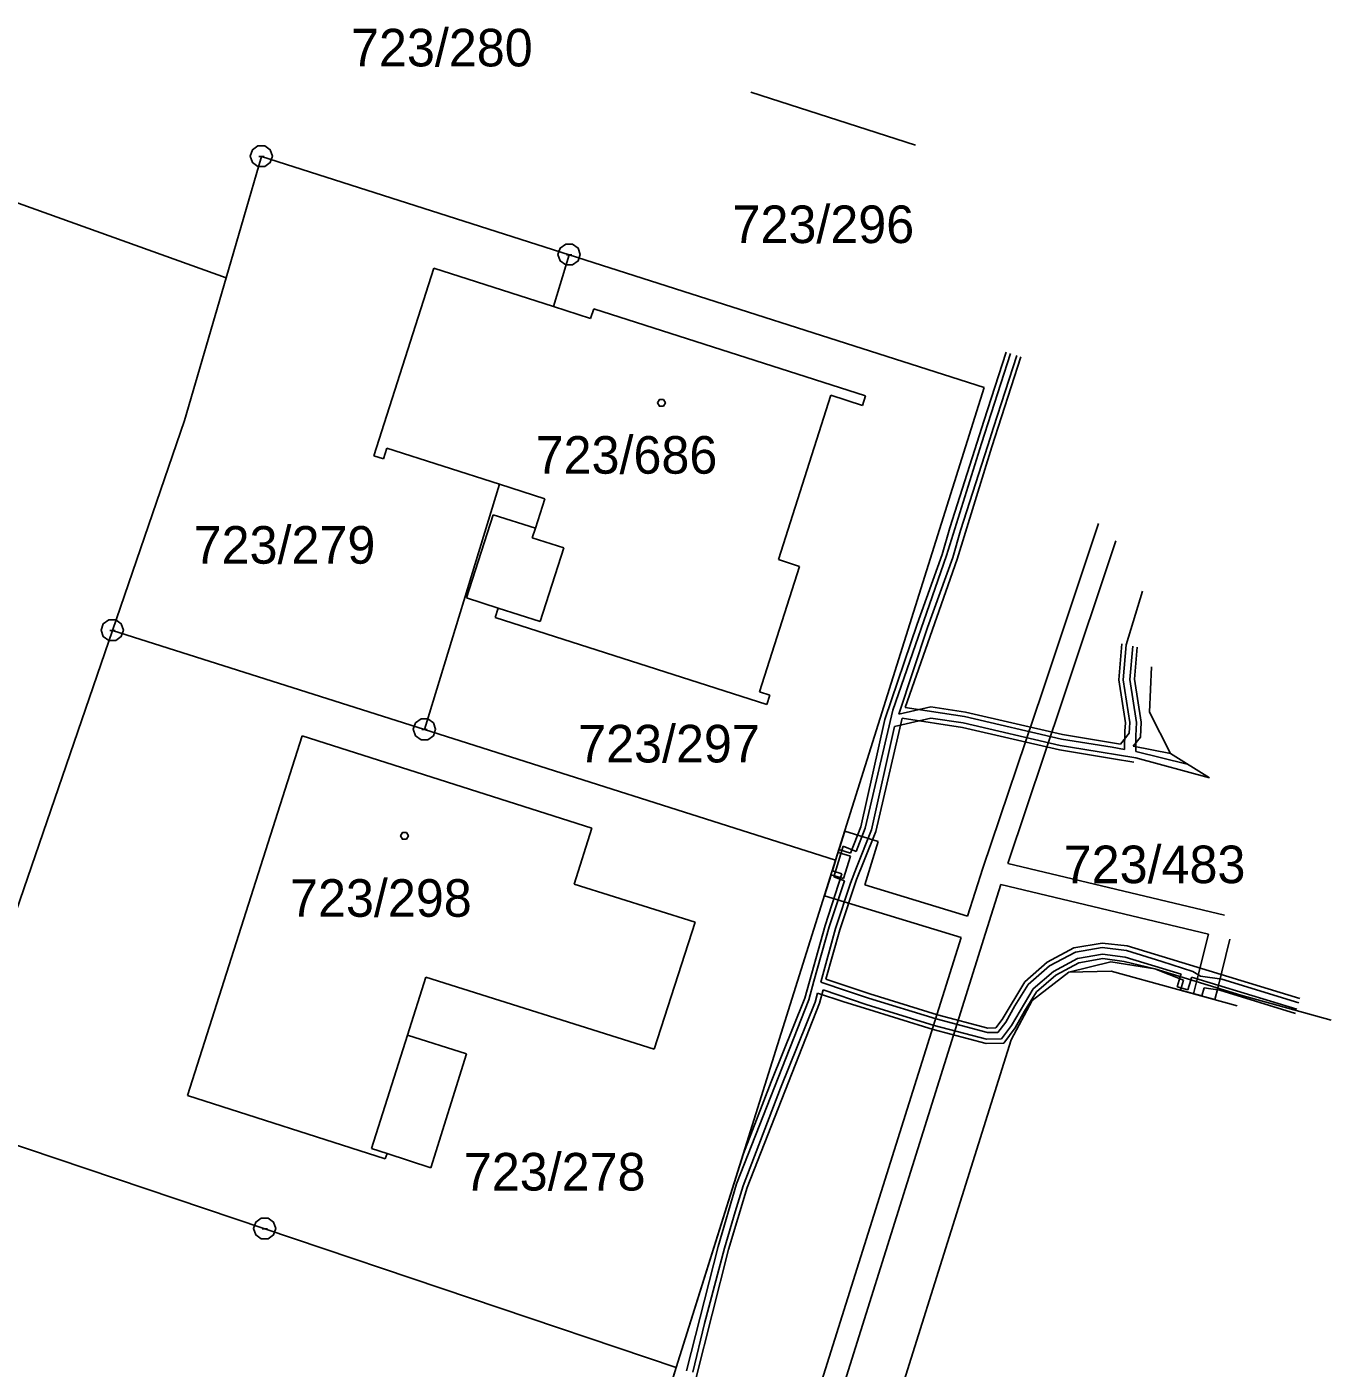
# Model space of a CAD drawing. Extents: x -759060 to -757386, y -1172273 to -1170948.
# Drawn here: x -757479 to -757420, y -1171073 to -1171012.4 of the extents above; entities that cross this region are included whole.
import ezdxf

# ---------------------------------------------------------------- set-up
doc = ezdxf.new("R2010")
doc.units = 0
for name, color, linetype in [('Vrstva 1', 7, 'Continuous'), ('Vrstva 12', 7, 'Continuous'), ('Vrstva 13', 7, 'Continuous'), ('Vrstva 2', 7, 'Continuous'), ('Vrstva 4', 7, 'Continuous'), ('Vrstva 5', 7, 'Continuous'), ('Vrstva 7', 7, 'Continuous'), ('Vrstva 8', 7, 'Continuous')]:
    doc.layers.add(name, color=color, linetype=linetype)

msp = doc.modelspace()

# ---------------------------------------------------------------- linework, layer by layer
at = {"layer": 'Vrstva 1'}
for p, q in [((-757438.84, -1171017.71), (-757446.28, -1171015.32)), ((-757446.28, -1171015.32), (-757446.28, -1171015.32)), ((-757470.02, -1171023.71), (-757490.64, -1171016.31)), ((-757438.84, -1171017.71), (-757438.84, -1171017.71)), ((-757468.42, -1171018.22), (-757470.02, -1171023.71)), ((-757454.5, -1171022.67), (-757468.42, -1171018.22)), ((-757468.42, -1171018.22), (-757468.42, -1171018.22)), ((-757455.21, -1171025.01), (-757454.5, -1171022.67)), ((-757435.73, -1171028.67), (-757454.5, -1171022.67)), ((-757454.5, -1171022.67), (-757454.5, -1171022.67)), ((-757463.33, -1171031.76), (-757460.62, -1171023.28)), ((-757460.62, -1171023.28), (-757455.21, -1171025.01)), ((-757470.02, -1171023.71), (-757471.9, -1171030.17)), ((-757455.21, -1171025.01), (-757453.53, -1171025.55)), ((-757453.53, -1171025.55), (-757453.39, -1171025.12)), ((-757453.39, -1171025.12), (-757441.1, -1171029.05)), ((-757435.73, -1171028.67), (-757442.45, -1171050.05)), ((-757435.73, -1171028.67), (-757435.73, -1171028.67)), ((-757442.67, -1171029.02), (-757445.04, -1171036.45)), ((-757441.24, -1171029.48), (-757442.67, -1171029.02)), ((-757441.1, -1171029.05), (-757441.24, -1171029.48)), ((-757471.9, -1171030.17), (-757475.16, -1171039.66)), ((-757462.9, -1171031.9), (-757463.33, -1171031.76)), ((-757462.75, -1171031.42), (-757462.9, -1171031.9)), ((-757457.66, -1171033.05), (-757462.75, -1171031.42)), ((-757461.04, -1171044.14), (-757457.66, -1171033.05)), ((-757455.61, -1171033.71), (-757457.66, -1171033.05)), ((-757456.03, -1171035.04), (-757455.61, -1171033.71)), ((-757459.14, -1171038.19), (-757457.94, -1171034.43)), ((-757457.94, -1171034.43), (-757456.03, -1171035.04)), ((-757444.09, -1171036.76), (-757445.9, -1171042.43)), ((-757445.04, -1171036.45), (-757444.09, -1171036.76)), ((-757457.71, -1171038.65), (-757459.14, -1171038.19)), ((-757457.85, -1171039.08), (-757457.71, -1171038.65)), ((-757445.56, -1171043.01), (-757457.85, -1171039.08)), ((-757475.16, -1171039.66), (-757482.77, -1171061.83)), ((-757461.04, -1171044.14), (-757475.16, -1171039.66)), ((-757428.17, -1171041.31), (-757428.26, -1171043.35)), ((-757428.17, -1171041.31), (-757428.17, -1171041.31)), ((-757445.9, -1171042.43), (-757445.43, -1171042.58)), ((-757445.43, -1171042.58), (-757445.56, -1171043.01)), ((-757428.26, -1171043.35), (-757428.26, -1171043.35)), ((-757428.26, -1171043.35), (-757427.3, -1171045.23)), ((-757471.77, -1171060.69), (-757466.58, -1171044.43)), ((-757466.58, -1171044.43), (-757453.48, -1171048.6)), ((-757442.45, -1171050.05), (-757461.04, -1171044.14)), ((-757427.3, -1171045.23), (-757425.55, -1171046.32)), ((-757425.55, -1171046.32), (-757425.55, -1171046.32)), ((-757453.48, -1171048.6), (-757454.28, -1171051.13)), ((-757442.45, -1171050.05), (-757449.66, -1171073)), ((-757454.28, -1171051.13), (-757448.8, -1171052.86)), ((-757448.8, -1171052.86), (-757450.66, -1171058.6)), ((-757431.91, -1171055.11), (-757430, -1171054.64)), ((-757430, -1171054.64), (-757428.02, -1171054.97)), ((-757428.02, -1171054.97), (-757424.13, -1171056.16)), ((-757460.99, -1171055.34), (-757461.82, -1171057.96)), ((-757450.66, -1171058.6), (-757460.99, -1171055.34)), ((-757433.57, -1171056.39), (-757431.91, -1171055.11)), ((-757431.91, -1171055.11), (-757429.99, -1171055.07)), ((-757429.99, -1171055.07), (-757424.29, -1171056.63)), ((-757424.13, -1171056.16), (-757420.04, -1171057.29)), ((-757434.52, -1171058.18), (-757433.57, -1171056.39)), ((-757424.29, -1171056.63), (-757424.29, -1171056.63)), ((-757420.04, -1171057.29), (-757420.04, -1171057.29)), ((-757461.82, -1171057.96), (-757459.14, -1171058.81)), ((-757445.57, -1171093.36), (-757434.52, -1171058.18)), ((-757459.14, -1171058.81), (-757460.76, -1171063.97)), ((-757462.82, -1171063.55), (-757471.77, -1171060.69)), ((-757482.77, -1171061.83), (-757468.27, -1171066.72)), ((-757462.73, -1171063.32), (-757462.82, -1171063.55)), ((-757460.76, -1171063.97), (-757462.73, -1171063.32)), ((-757449.66, -1171073), (-757468.27, -1171066.72)), ((-757449.66, -1171073), (-757453.18, -1171084.22))]:
    msp.add_line(p, q, dxfattribs=at)
at = {"layer": 'Vrstva 12'}
for p, q in [((-757438.84, -1171017.71), (-757446.28, -1171015.32)), ((-757446.28, -1171015.32), (-757446.28, -1171015.32)), ((-757438.84, -1171017.71), (-757438.84, -1171017.71)), ((-757463.33, -1171031.76), (-757460.62, -1171023.28)), ((-757460.62, -1171023.28), (-757455.21, -1171025.01)), ((-757455.21, -1171025.01), (-757453.53, -1171025.55)), ((-757453.53, -1171025.55), (-757453.39, -1171025.12)), ((-757453.39, -1171025.12), (-757441.1, -1171029.05)), ((-757442.67, -1171029.02), (-757445.04, -1171036.45)), ((-757441.24, -1171029.48), (-757442.67, -1171029.02)), ((-757441.1, -1171029.05), (-757441.24, -1171029.48)), ((-757462.9, -1171031.9), (-757463.33, -1171031.76)), ((-757462.75, -1171031.42), (-757462.9, -1171031.9)), ((-757457.66, -1171033.05), (-757462.75, -1171031.42)), ((-757455.61, -1171033.71), (-757457.66, -1171033.05)), ((-757456.03, -1171035.04), (-757455.61, -1171033.71)), ((-757456.17, -1171035.47), (-757456.03, -1171035.04)), ((-757454.74, -1171035.93), (-757456.17, -1171035.47)), ((-757455.81, -1171039.26), (-757454.74, -1171035.93)), ((-757444.09, -1171036.76), (-757445.9, -1171042.43)), ((-757445.04, -1171036.45), (-757444.09, -1171036.76)), ((-757457.85, -1171039.08), (-757457.71, -1171038.65)), ((-757445.56, -1171043.01), (-757457.85, -1171039.08)), ((-757457.71, -1171038.65), (-757455.81, -1171039.26)), ((-757445.9, -1171042.43), (-757445.43, -1171042.58)), ((-757445.43, -1171042.58), (-757445.56, -1171043.01)), ((-757471.77, -1171060.69), (-757466.58, -1171044.43)), ((-757466.58, -1171044.43), (-757453.48, -1171048.6)), ((-757453.48, -1171048.6), (-757454.28, -1171051.13)), ((-757454.28, -1171051.13), (-757448.8, -1171052.86)), ((-757448.8, -1171052.86), (-757450.66, -1171058.6)), ((-757460.99, -1171055.34), (-757461.82, -1171057.96)), ((-757450.66, -1171058.6), (-757460.99, -1171055.34)), ((-757461.82, -1171057.96), (-757463.44, -1171063.09)), ((-757462.82, -1171063.55), (-757471.77, -1171060.69)), ((-757463.44, -1171063.09), (-757462.73, -1171063.32)), ((-757462.73, -1171063.32), (-757462.82, -1171063.55))]:
    msp.add_line(p, q, dxfattribs=at)
at = {"layer": 'Vrstva 13'}
for p, q in [((-757435.75, -1171030.2), (-757434.74, -1171027.08)), ((-757434.74, -1171027.08), (-757434.74, -1171027.08)), ((-757435.86, -1171031.21), (-757434.55, -1171027.14)), ((-757434.07, -1171027.29), (-757435.38, -1171031.36)), ((-757434.26, -1171027.22), (-757435.31, -1171030.48)), ((-757434.55, -1171027.14), (-757434.55, -1171027.14)), ((-757434.26, -1171027.22), (-757434.26, -1171027.22)), ((-757434.07, -1171027.29), (-757434.07, -1171027.29)), ((-757436.05, -1171031.14), (-757435.75, -1171030.2)), ((-757435.31, -1171030.48), (-757435.57, -1171031.3)), ((-757437.44, -1171036.27), (-757435.86, -1171031.21)), ((-757437.29, -1171035.02), (-757436.05, -1171031.14)), ((-757435.38, -1171031.36), (-757436.96, -1171036.43)), ((-757435.57, -1171031.3), (-757436.81, -1171035.14)), ((-757433.1, -1171042.42), (-757430.57, -1171034.83)), ((-757430.57, -1171034.83), (-757430.57, -1171034.83)), ((-757437.63, -1171036.22), (-757437.29, -1171035.02)), ((-757436.81, -1171035.14), (-757437.15, -1171036.36)), ((-757429.78, -1171035.6), (-757432.16, -1171042.74)), ((-757429.78, -1171035.6), (-757429.78, -1171035.6)), ((-757438.77, -1171039.38), (-757437.63, -1171036.22)), ((-757439.87, -1171043.27), (-757437.44, -1171036.27)), ((-757436.96, -1171036.43), (-757439.3, -1171043.15)), ((-757437.15, -1171036.36), (-757438.29, -1171039.52)), ((-757429.31, -1171040.31), (-757428.57, -1171037.89)), ((-757428.57, -1171037.89), (-757428.57, -1171037.89)), ((-757440.22, -1171043.68), (-757438.77, -1171039.38)), ((-757438.29, -1171039.52), (-757439.6, -1171043.45)), ((-757429.64, -1171041.9), (-757429.51, -1171040.27)), ((-757429.51, -1171040.27), (-757429.51, -1171040.27)), ((-757429.44, -1171041.89), (-757429.31, -1171040.31)), ((-757429.01, -1171040.37), (-757429.14, -1171041.88)), ((-757429.01, -1171040.37), (-757429.01, -1171040.37)), ((-757428.81, -1171040.41), (-757428.94, -1171041.87)), ((-757428.81, -1171040.41), (-757428.81, -1171040.41)), ((-757429.34, -1171043.84), (-757429.64, -1171041.9)), ((-757429.14, -1171043.83), (-757429.44, -1171041.89)), ((-757429.14, -1171041.88), (-757428.84, -1171043.82)), ((-757428.94, -1171041.87), (-757428.64, -1171043.81)), ((-757435.8, -1171050.41), (-757433.1, -1171042.42)), ((-757432.16, -1171042.74), (-757434.67, -1171050.2)), ((-757441.12, -1171048.6), (-757439.87, -1171043.27)), ((-757439.6, -1171043.45), (-757438.15, -1171043.12)), ((-757439.3, -1171043.15), (-757436.62, -1171043.55)), ((-757438.15, -1171043.12), (-757436.58, -1171043.36)), ((-757436.58, -1171043.36), (-757432.19, -1171044.36)), ((-757441.31, -1171048.54), (-757440.22, -1171043.68)), ((-757439.79, -1171044.01), (-757440.83, -1171048.68)), ((-757439.44, -1171043.63), (-757440.64, -1171048.75)), ((-757438.15, -1171043.62), (-757439.79, -1171044.01)), ((-757436.72, -1171044.05), (-757439.44, -1171043.63)), ((-757436.68, -1171043.84), (-757438.15, -1171043.62)), ((-757432.33, -1171045.06), (-757436.72, -1171044.05)), ((-757432.29, -1171044.86), (-757436.68, -1171043.84)), ((-757436.62, -1171043.55), (-757432.23, -1171044.57)), ((-757429.37, -1171044.22), (-757429.34, -1171043.84)), ((-757429.17, -1171044.31), (-757429.14, -1171043.83)), ((-757428.84, -1171043.82), (-757428.88, -1171044.42)), ((-757428.64, -1171043.81), (-757428.67, -1171044.49)), ((-757432.23, -1171044.57), (-757429.95, -1171044.94)), ((-757432.19, -1171044.36), (-757431.19, -1171044.53)), ((-757431.19, -1171044.53), (-757429.57, -1171044.8)), ((-757429.57, -1171044.8), (-757429.17, -1171044.31)), ((-757429.38, -1171045.04), (-757429.37, -1171044.22)), ((-757428.67, -1171044.49), (-757428.99, -1171044.89)), ((-757428.88, -1171044.42), (-757428.87, -1171045.13)), ((-757429.89, -1171045.46), (-757432.33, -1171045.06)), ((-757431.27, -1171045.03), (-757432.29, -1171044.86)), ((-757428.88, -1171045.42), (-757431.27, -1171045.03)), ((-757429.95, -1171044.94), (-757429.38, -1171045.04)), ((-757428.99, -1171044.89), (-757427.3, -1171045.23)), ((-757428.87, -1171045.13), (-757426.55, -1171045.7)), ((-757427.3, -1171045.23), (-757427.3, -1171045.23)), ((-757428.97, -1171045.62), (-757429.89, -1171045.46)), ((-757428.97, -1171045.62), (-757428.97, -1171045.62)), ((-757425.55, -1171046.32), (-757428.88, -1171045.42)), ((-757426.55, -1171045.7), (-757426.55, -1171045.7)), ((-757425.55, -1171046.32), (-757425.55, -1171046.32)), ((-757442.34, -1171049.7), (-757442.04, -1171048.74)), ((-757442.04, -1171048.74), (-757440.52, -1171049.21)), ((-757441.78, -1171049.73), (-757441.31, -1171048.54)), ((-757441.53, -1171049.65), (-757441.12, -1171048.6)), ((-757440.83, -1171048.68), (-757441.51, -1171050.38)), ((-757440.64, -1171048.75), (-757441.16, -1171050.06)), ((-757442.54, -1171050.8), (-757442.11, -1171049.42)), ((-757442.11, -1171049.42), (-757441.53, -1171049.65)), ((-757440.52, -1171049.21), (-757441.13, -1171051.17)), ((-757442.6, -1171050.53), (-757442.3, -1171049.57)), ((-757441.78, -1171049.87), (-757442.34, -1171049.7)), ((-757442.3, -1171049.57), (-757441.78, -1171049.73)), ((-757442.09, -1171050.88), (-757441.78, -1171049.87)), ((-757441.16, -1171050.06), (-757441.51, -1171050.93)), ((-757442.96, -1171051.66), (-757442.66, -1171050.72)), ((-757442.93, -1171053), (-757442.17, -1171050.66)), ((-757442.66, -1171050.72), (-757442.09, -1171050.88)), ((-757442.17, -1171050.66), (-757442.6, -1171050.53)), ((-757441.51, -1171050.38), (-757441.78, -1171051.09)), ((-757436.48, -1171052.58), (-757435.8, -1171050.41)), ((-757434.67, -1171050.2), (-757424.86, -1171052.53)), ((-757442.74, -1171053.06), (-757442.05, -1171050.99)), ((-757442.05, -1171050.99), (-757442.54, -1171050.8)), ((-757441.78, -1171051.09), (-757442.45, -1171053.14)), ((-757441.51, -1171050.93), (-757442.26, -1171053.2)), ((-757441.13, -1171051.17), (-757436.48, -1171052.58)), ((-757434.98, -1171051.15), (-757435.67, -1171053.35)), ((-757425.59, -1171053.39), (-757434.98, -1171051.15)), ((-757436.78, -1171053.54), (-757442.96, -1171051.66)), ((-757424.86, -1171052.53), (-757424.86, -1171052.53)), ((-757443.85, -1171056.29), (-757442.93, -1171053)), ((-757443.43, -1171055.52), (-757442.74, -1171053.06)), ((-757442.45, -1171053.14), (-757443.12, -1171055.56)), ((-757442.26, -1171053.2), (-757442.89, -1171055.43)), ((-757443.72, -1171075.65), (-757436.78, -1171053.54)), ((-757435.67, -1171053.35), (-757442.91, -1171076.42)), ((-757431.68, -1171054.02), (-757430.4, -1171053.8)), ((-757430.4, -1171053.8), (-757429.26, -1171053.93)), ((-757426.13, -1171055.55), (-757425.59, -1171053.39)), ((-757424.62, -1171053.62), (-757425.17, -1171055.84)), ((-757424.62, -1171053.62), (-757424.62, -1171053.62)), ((-757432.88, -1171054.66), (-757431.68, -1171054.02)), ((-757432.78, -1171054.83), (-757431.61, -1171054.21)), ((-757431.61, -1171054.21), (-757430.39, -1171054)), ((-757430.38, -1171054.3), (-757431.52, -1171054.5)), ((-757430.39, -1171054), (-757429.3, -1171054.13)), ((-757429.36, -1171054.43), (-757430.38, -1171054.3)), ((-757429.3, -1171054.13), (-757427.7, -1171054.63)), ((-757429.26, -1171053.93), (-757426.45, -1171054.79)), ((-757433.89, -1171055.55), (-757432.88, -1171054.66)), ((-757433.74, -1171055.67), (-757432.78, -1171054.83)), ((-757431.52, -1171054.5), (-757432.6, -1171055.08)), ((-757431.45, -1171054.69), (-757432.49, -1171055.25)), ((-757430.37, -1171054.5), (-757431.45, -1171054.69)), ((-757429.4, -1171054.63), (-757430.37, -1171054.5)), ((-757428.02, -1171054.97), (-757429.4, -1171054.63)), ((-757426.83, -1171055.2), (-757429.36, -1171054.43)), ((-757426.72, -1171055.47), (-757428.02, -1171054.97)), ((-757427.7, -1171054.63), (-757426.29, -1171055.09)), ((-757426.45, -1171054.79), (-757421.45, -1171056.31)), ((-757443.66, -1171056.36), (-757443.43, -1171055.52)), ((-757443.12, -1171055.56), (-757441.92, -1171055.97)), ((-757442.89, -1171055.43), (-757440.91, -1171056.09)), ((-757434.92, -1171057.25), (-757433.89, -1171055.55)), ((-757432.6, -1171055.08), (-757433.51, -1171055.87)), ((-757432.49, -1171055.25), (-757433.36, -1171056.01)), ((-757427, -1171055.78), (-757426.87, -1171055.32)), ((-757426.87, -1171055.32), (-757426.83, -1171055.2)), ((-757426.86, -1171055.93), (-757426.72, -1171055.47)), ((-757426.39, -1171055.47), (-757426.52, -1171055.92)), ((-757426.35, -1171055.34), (-757426.39, -1171055.47)), ((-757421.59, -1171056.79), (-757426.35, -1171055.34)), ((-757426.29, -1171055.09), (-757425.95, -1171055.3)), ((-757426.26, -1171056.09), (-757426.13, -1171055.55)), ((-757425.95, -1171055.3), (-757424.98, -1171055.43)), ((-757424.98, -1171055.43), (-757421.51, -1171056.5)), ((-757443.27, -1171056.07), (-757443.37, -1171056.47)), ((-757442.08, -1171056.45), (-757443.27, -1171056.07)), ((-757443.02, -1171055.91), (-757443.18, -1171056.52)), ((-757441.07, -1171056.57), (-757443.02, -1171055.91)), ((-757441.92, -1171055.97), (-757440.96, -1171056.29)), ((-757440.91, -1171056.09), (-757437.85, -1171057.04)), ((-757433.51, -1171055.87), (-757434.5, -1171057.53)), ((-757434.35, -1171056.64), (-757433.74, -1171055.67)), ((-757433.36, -1171056.01), (-757433.91, -1171056.88)), ((-757426.52, -1171055.92), (-757427, -1171055.78)), ((-757425.89, -1171056.19), (-757426.86, -1171055.93)), ((-757425.3, -1171056.35), (-757426.26, -1171056.09)), ((-757425.78, -1171055.83), (-757425.89, -1171056.19)), ((-757425.08, -1171055.93), (-757425.78, -1171055.83)), ((-757425.17, -1171055.84), (-757425.3, -1171056.35)), ((-757421.65, -1171056.98), (-757425.08, -1171055.93)), ((-757446.93, -1171064.69), (-757443.66, -1171056.36)), ((-757443.18, -1171056.52), (-757446.45, -1171064.85)), ((-757445.37, -1171060.08), (-757443.85, -1171056.29)), ((-757443.37, -1171056.47), (-757444.95, -1171060.36)), ((-757441.14, -1171056.75), (-757442.08, -1171056.45)), ((-757438.04, -1171057.71), (-757441.14, -1171056.75)), ((-757437.99, -1171057.52), (-757441.07, -1171056.57)), ((-757440.96, -1171056.29), (-757437.9, -1171057.23)), ((-757434.75, -1171057.37), (-757434.35, -1171056.64)), ((-757421.59, -1171056.79), (-757421.59, -1171056.79)), ((-757421.51, -1171056.5), (-757421.51, -1171056.5)), ((-757421.45, -1171056.31), (-757421.45, -1171056.31)), ((-757437.9, -1171057.23), (-757435.59, -1171057.84)), ((-757437.85, -1171057.04), (-757435.57, -1171057.64)), ((-757435.21, -1171057.63), (-757434.92, -1171057.25)), ((-757435.12, -1171057.84), (-757434.75, -1171057.37)), ((-757433.91, -1171056.88), (-757434.33, -1171057.63)), ((-757421.65, -1171056.98), (-757421.65, -1171056.98)), ((-757435.65, -1171058.34), (-757438.04, -1171057.71)), ((-757435.63, -1171058.14), (-757437.99, -1171057.52)), ((-757435.59, -1171057.84), (-757435.12, -1171057.84)), ((-757435.57, -1171057.64), (-757435.21, -1171057.63)), ((-757434.5, -1171057.53), (-757434.95, -1171058.13)), ((-757434.33, -1171057.63), (-757434.85, -1171058.33)), ((-757434.85, -1171058.33), (-757435.65, -1171058.34)), ((-757434.95, -1171058.13), (-757435.63, -1171058.14)), ((-757444.95, -1171060.36), (-757446.64, -1171064.78)), ((-757446.62, -1171063.32), (-757445.37, -1171060.08)), ((-757449.66, -1171073), (-757446.62, -1171063.32)), ((-757447.77, -1171067.52), (-757446.93, -1171064.69)), ((-757446.45, -1171064.85), (-757447.29, -1171067.66)), ((-757446.64, -1171064.78), (-757446.99, -1171065.96)), ((-757446.99, -1171065.96), (-757447.48, -1171067.6)), ((-757449.2, -1171073.14), (-757447.77, -1171067.52)), ((-757447.29, -1171067.66), (-757448.78, -1171073.5)), ((-757447.48, -1171067.6), (-757448.38, -1171071)), ((-757448.38, -1171071), (-757448.91, -1171073.2)), ((-757450.03, -1171074.19), (-757449.66, -1171073))]:
    msp.add_line(p, q, dxfattribs=at)
at = {"layer": 'Vrstva 4'}
for p, q in [((-757456.17, -1171035.47), (-757456.03, -1171035.04)), ((-757454.74, -1171035.93), (-757456.17, -1171035.47)), ((-757455.81, -1171039.26), (-757454.74, -1171035.93)), ((-757457.71, -1171038.65), (-757455.81, -1171039.26)), ((-757461.82, -1171057.96), (-757463.44, -1171063.09)), ((-757463.44, -1171063.09), (-757462.73, -1171063.32))]:
    msp.add_line(p, q, dxfattribs=at)
at = {"layer": 'Vrstva 5'}
for points in [[(-757450.24, -1171029.22), (-757450.15, -1171029.37), (-757450.24, -1171029.52), (-757450.42, -1171029.52), (-757450.51, -1171029.37), (-757450.42, -1171029.22)], [(-757461.86, -1171048.8), (-757461.77, -1171048.95), (-757461.86, -1171049.1), (-757462.04, -1171049.1), (-757462.13, -1171048.95), (-757462.04, -1171048.8)]]:
    msp.add_lwpolyline(points, close=True, dxfattribs=at)
at = {"layer": 'Vrstva 8'}
for p, q in [((-757468.54, -1171018.22), (-757468.3, -1171018.22)), ((-757454.62, -1171022.67), (-757454.38, -1171022.67)), ((-757475.28, -1171039.66), (-757475.04, -1171039.66)), ((-757461.16, -1171044.14), (-757460.92, -1171044.14)), ((-757468.39, -1171066.72), (-757468.15, -1171066.72))]:
    msp.add_line(p, q, dxfattribs=at)
for points in [[(-757468.27, -1171017.74), (-757468.02, -1171017.92), (-757467.92, -1171018.21), (-757468.02, -1171018.5), (-757468.27, -1171018.68), (-757468.58, -1171018.68), (-757468.83, -1171018.5), (-757468.93, -1171018.21), (-757468.83, -1171017.92), (-757468.58, -1171017.74)], [(-757454.35, -1171022.19), (-757454.1, -1171022.37), (-757454, -1171022.66), (-757454.1, -1171022.95), (-757454.35, -1171023.13), (-757454.66, -1171023.13), (-757454.91, -1171022.95), (-757455.01, -1171022.66), (-757454.91, -1171022.37), (-757454.66, -1171022.19)], [(-757475.01, -1171039.18), (-757474.76, -1171039.36), (-757474.66, -1171039.65), (-757474.76, -1171039.94), (-757475.01, -1171040.12), (-757475.32, -1171040.12), (-757475.57, -1171039.94), (-757475.67, -1171039.65), (-757475.57, -1171039.36), (-757475.32, -1171039.18)], [(-757460.89, -1171043.66), (-757460.64, -1171043.84), (-757460.54, -1171044.13), (-757460.64, -1171044.42), (-757460.89, -1171044.6), (-757461.2, -1171044.6), (-757461.45, -1171044.42), (-757461.55, -1171044.13), (-757461.45, -1171043.84), (-757461.2, -1171043.66)], [(-757468.12, -1171066.24), (-757467.87, -1171066.42), (-757467.77, -1171066.71), (-757467.87, -1171067), (-757468.12, -1171067.18), (-757468.43, -1171067.18), (-757468.68, -1171067), (-757468.78, -1171066.71), (-757468.68, -1171066.42), (-757468.43, -1171066.24)]]:
    msp.add_lwpolyline(points, close=True, dxfattribs=at)

# ---------------------------------------------------------------- texts
at = {"layer": 'Vrstva 2'}
for s, p in [('723/280', (-757464.369, -1171014.15)), ('723/296', (-757447.116, -1171022.14)), ('723/686', (-757456.019, -1171032.57)), ('723/279', (-757471.486, -1171036.64)), ('723/297', (-757454.096, -1171045.63)), ('723/298', (-757467.126, -1171052.61)), ('723/278', (-757459.266, -1171064.99))]:
    msp.add_text(s, height=1.7, dxfattribs=at).set_placement(p)
at = {"layer": 'Vrstva 7'}
msp.add_text('723/483', height=1.7, dxfattribs=at).set_placement((-757432.136, -1171051.09))

doc.saveas('drawing.dxf')
